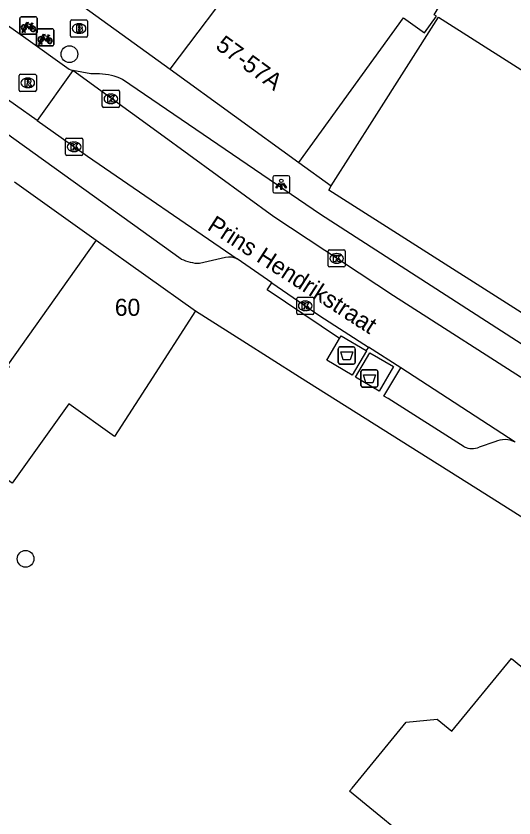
# Model space of a CAD drawing. Extents: x 160664 to 161506, y 382245 to 383288.
# Drawn here: x 161008.69 to 161037.82, y 383009.95 to 383056.85 of the extents above; entities that cross this region are included whole.
import ezdxf

# ---------------------------------------------------------------- set-up
doc = ezdxf.new("R2010")
doc.units = 0
for name, color, linetype in [('IMGEO_Afval_apart_plaats', 7, 'Continuous'), ('IMGEO_Boom', 7, 'Continuous'), ('IMGEO_Brandkraan', 7, 'Continuous'), ('IMGEO_Fietsenrek', 7, 'Continuous'), ('IMGEO_Kolk', 7, 'Continuous'), ('IMGEO_Lichtpunt', 7, 'Continuous'), ('IMGEO_Muur', 7, 'Continuous'), ('IMGEO_Openbare_ruimte_label', 7, 'Continuous'), ('IMGEO_Pand', 7, 'Continuous'), ('IMGEO_Pand_nummerreeks', 7, 'Continuous'), ('IMGEO_Rijbaan_lokaal_open', 7, 'Continuous'), ('IMGEO_Rioolput', 7, 'Continuous'), ('IMGEO_Voetpad_gesloten', 7, 'Continuous'), ('IMGEO_Voetpad_open', 7, 'Continuous')]:
    doc.layers.add(name, color=color, linetype=linetype)

msp = doc.modelspace()

# ---------------------------------------------------------------- linework, layer by layer
at = {"layer": 'IMGEO_Afval_apart_plaats'}
for p, q in [((161027.641, 383037.497), (161028.431, 383037.497)), ((161028.431, 383037.497), (161027.641, 383037.497)), ((161027.541, 383036.597), (161027.541, 383037.397)), ((161027.541, 383037.397), (161027.541, 383036.597)), ((161028.531, 383037.397), (161028.531, 383036.597)), ((161028.531, 383036.597), (161028.531, 383037.397)), ((161028.431, 383036.497), (161027.641, 383036.497)), ((161027.641, 383036.497), (161028.431, 383036.497)), ((161028.868, 383035.253), (161028.868, 383036.053)), ((161028.868, 383036.053), (161028.868, 383035.253)), ((161028.968, 383036.153), (161029.758, 383036.153)), ((161029.758, 383036.153), (161028.968, 383036.153)), ((161029.858, 383036.053), (161029.858, 383035.253)), ((161029.858, 383035.253), (161029.858, 383036.053)), ((161029.758, 383035.153), (161028.968, 383035.153)), ((161028.968, 383035.153), (161029.758, 383035.153))]:
    msp.add_line(p, q, dxfattribs=at)
for points in [[(161027.684, 383037.211), (161028.388, 383037.211), (161028.239, 383036.741), (161027.833, 383036.741), (161027.684, 383037.211)], [(161029.011, 383035.867), (161029.715, 383035.867), (161029.566, 383035.397), (161029.16, 383035.397), (161029.011, 383035.867)]]:
    msp.add_lwpolyline(points, dxfattribs=at)
for centre, start, end in [((161027.641, 383037.397), 90, 180), ((161027.641, 383037.397), 90, 180), ((161028.431, 383037.397), 0, 90), ((161028.431, 383037.397), 360, 90), ((161027.641, 383036.597), 180, 270), ((161027.641, 383036.597), 180, 270), ((161028.431, 383036.597), 270, 0), ((161028.431, 383036.597), 270, 0), ((161028.968, 383036.053), 90, 180), ((161028.968, 383036.053), 90, 180), ((161029.758, 383036.053), 0, 90), ((161029.758, 383036.053), 360, 90), ((161028.968, 383035.253), 180, 270), ((161028.968, 383035.253), 180, 270), ((161029.758, 383035.253), 270, 0), ((161029.758, 383035.253), 270, 0)]:
    msp.add_arc(centre, 0.1, start, end, dxfattribs=at)
at = {"layer": 'IMGEO_Boom'}
for centre in [(161011.813, 383054.621), (161009.25, 383025.106)]:
    msp.add_circle(centre, 0.489, dxfattribs=at)
at = {"layer": 'IMGEO_Brandkraan'}
for p, q in [((161011.877, 383055.695), (161011.877, 383056.547)), ((161011.952, 383056.621), (161012.804, 383056.621)), ((161012.365, 383056.401), (161012.39, 383056.401)), ((161012.878, 383056.547), (161012.878, 383055.695)), ((161012.388, 383055.841), (161012.363, 383055.841)), ((161012.804, 383055.621), (161011.952, 383055.621))]:
    msp.add_line(p, q, dxfattribs=at)
for points in [[(161011.877, 383055.695), (161011.877, 383056.547)], [(161011.952, 383056.621), (161012.804, 383056.621)], [(161012.225, 383056.321), (161012.225, 383055.921), (161012.438, 383055.921)], [(161012.456, 383056.321), (161012.225, 383056.321)], [(161012.404, 383056.24), (161012.35, 383056.24), (161012.35, 383056.164)], [(161012.878, 383056.547), (161012.878, 383055.695)], [(161012.35, 383056.164), (161012.403, 383056.164)], [(161012.412, 383056.088), (161012.35, 383056.088), (161012.35, 383056.007)], [(161012.35, 383056.007), (161012.412, 383056.007)], [(161012.804, 383055.621), (161011.952, 383055.621)]]:
    msp.add_lwpolyline(points, dxfattribs=at)
for centre, radius, start, end in [((161011.954, 383056.545), 0.0765, 91.552, 178.448), ((161011.954, 383056.545), 0.0765, 91.552, 178.448), ((161012.405, 383056.202), 0.0379, 267.8285, 90.9355), ((161012.46, 383056.176), 0.145, 59.4692, 91.5367), ((161012.485, 383056.223), 0.0922, 285.5137, 58.1501), ((161012.802, 383056.545), 0.0765, 1.552, 88.448), ((161012.802, 383056.545), 0.0765, 1.552, 88.448), ((161012.413, 383056.047), 0.0404, 269.8759, 90.5077), ((161012.444, 383056.172), 0.251, 268.6676, 293.5347), ((161012.49, 383056.031), 0.105, 301.3115, 78.989), ((161011.954, 383055.697), 0.0765, 181.552, 268.448), ((161011.954, 383055.697), 0.0765, 181.552, 268.448), ((161012.802, 383055.697), 0.0765, 271.552, 358.448), ((161012.802, 383055.697), 0.0765, 271.552, 358.448)]:
    msp.add_arc(centre, radius, start, end, dxfattribs=at)
for centre, major_axis, ratio, start_param, end_param in [((161012.364, 383056.121), (-0.387, 0.002), 0.722429, 4.712389, 7.853982), ((161012.389, 383056.121), (-0.39, 0.002), 0.717154, 1.570796, 4.712389)]:
    msp.add_ellipse(centre, major_axis=major_axis, ratio=ratio, start_param=start_param, end_param=end_param, dxfattribs=at)
at = {"layer": 'IMGEO_Fietsenrek'}
for p, q in [((161008.918, 383055.874), (161008.918, 383056.715)), ((161008.918, 383056.715), (161008.918, 383055.874)), ((161008.993, 383056.799), (161009.834, 383056.799)), ((161009.834, 383056.799), (161008.993, 383056.799)), ((161009.918, 383056.724), (161009.918, 383055.883)), ((161009.918, 383055.883), (161009.918, 383056.724)), ((161009.605, 383056.348), (161009.641, 383056.253)), ((161009.843, 383055.799), (161009.002, 383055.799)), ((161009.002, 383055.799), (161009.843, 383055.799)), ((161009.045, 383055.883), (161009.084, 383056.043)), ((161009.079, 383055.883), (161009.045, 383055.883)), ((161009.114, 383056.031), (161009.079, 383055.883)), ((161009.156, 383056.055), (161009.155, 383056.059)), ((161009.197, 383055.883), (161009.163, 383056.025)), ((161009.187, 383056.066), (161009.188, 383056.059)), ((161009.195, 383056.029), (161009.23, 383055.883)), ((161009.23, 383055.883), (161009.197, 383055.883)), ((161009.894, 383055.176), (161009.894, 383056.017)), ((161009.894, 383056.017), (161009.894, 383055.176)), ((161009.969, 383056.101), (161010.81, 383056.101)), ((161010.81, 383056.101), (161009.969, 383056.101)), ((161010.894, 383056.026), (161010.894, 383055.185)), ((161010.894, 383055.185), (161010.894, 383056.026)), ((161010.021, 383055.185), (161010.06, 383055.345)), ((161010.09, 383055.333), (161010.055, 383055.185)), ((161010.132, 383055.357), (161010.131, 383055.361)), ((161010.173, 383055.185), (161010.139, 383055.327)), ((161010.163, 383055.368), (161010.164, 383055.361)), ((161010.171, 383055.331), (161010.206, 383055.185)), ((161010.581, 383055.65), (161010.617, 383055.555)), ((161010.819, 383055.101), (161009.978, 383055.101)), ((161009.978, 383055.101), (161010.819, 383055.101)), ((161010.055, 383055.185), (161010.021, 383055.185)), ((161010.206, 383055.185), (161010.173, 383055.185))]:
    msp.add_line(p, q, dxfattribs=at)
for points in [[(161009.252, 383056.273), (161009.2, 383056.183), (161009.16, 383056.158), (161009.161, 383056.205), (161009.216, 383056.299)], [(161009.231, 383056.325), (161009.326, 383056.489), (161009.412, 383056.475), (161009.414, 383056.466), (161009.358, 383056.455), (161009.331, 383056.41), (161009.587, 383056.369)], [(161009.527, 383056.081), (161009.477, 383056.081), (161009.286, 383056.332), (161009.267, 383056.3)], [(161009.574, 383056.344), (161009.317, 383056.385), (161009.3, 383056.356), (161009.467, 383056.136), (161009.574, 383056.344)], [(161009.622, 383056.246), (161009.592, 383056.323), (161009.483, 383056.105), (161009.526, 383056.105)], [(161009.556, 383056.105), (161009.676, 383056.104), (161009.632, 383056.218)], [(161009.652, 383056.225), (161009.707, 383056.08), (161009.557, 383056.08)], [(161009.587, 383056.369), (161009.612, 383056.418), (161009.606, 383056.422), (161009.583, 383056.426), (161009.571, 383056.433), (161009.57, 383056.436), (161009.572, 383056.441), (161009.667, 383056.426), (161009.669, 383056.416), (161009.659, 383056.403), (161009.647, 383056.397), (161009.633, 383056.403), (161009.605, 383056.348)], [(161010.207, 383055.627), (161010.302, 383055.791), (161010.388, 383055.777), (161010.39, 383055.768), (161010.334, 383055.757), (161010.307, 383055.712), (161010.563, 383055.671)], [(161010.563, 383055.671), (161010.588, 383055.72), (161010.582, 383055.724), (161010.559, 383055.728), (161010.547, 383055.735), (161010.546, 383055.738), (161010.548, 383055.743), (161010.643, 383055.728), (161010.645, 383055.718), (161010.635, 383055.705), (161010.623, 383055.699), (161010.609, 383055.705), (161010.581, 383055.65)], [(161010.228, 383055.575), (161010.176, 383055.485), (161010.136, 383055.46), (161010.137, 383055.507), (161010.192, 383055.601)], [(161010.503, 383055.383), (161010.453, 383055.383), (161010.262, 383055.634), (161010.243, 383055.602)], [(161010.55, 383055.646), (161010.293, 383055.687), (161010.276, 383055.658), (161010.443, 383055.438), (161010.55, 383055.646)], [(161010.598, 383055.548), (161010.568, 383055.625), (161010.459, 383055.407), (161010.502, 383055.407)], [(161010.532, 383055.407), (161010.652, 383055.406), (161010.608, 383055.52)], [(161010.628, 383055.527), (161010.683, 383055.382), (161010.533, 383055.382)]]:
    msp.add_lwpolyline(points, dxfattribs=at)
for centre, radius, start, end in [((161008.996, 383056.721), 0.0779, 92.4484, 184.2845), ((161008.996, 383056.721), 0.0779, 92.4484, 184.2845), ((161009.84, 383056.721), 0.0779, 2.4484, 94.2845), ((161009.84, 383056.721), 0.0779, 2.4484, 94.2845), ((161009.158, 383056.184), 0.159, 62.6766, 242.1369), ((161009.158, 383056.184), 0.129, 63.3192, 238.903), ((161009.158, 383056.184), 0.129, 283.6043, 43.4302), ((161009.158, 383056.184), 0.159, 283.5766, 46.6042), ((161009.685, 383056.1), 0.159, 113.3408, 178.3217), ((161009.685, 383056.1), 0.159, 187.0065, 105.7708), ((161009.685, 383056.1), 0.129, 113.923, 177.9556), ((161009.685, 383056.1), 0.129, 188.6715, 104.5883), ((161008.996, 383055.877), 0.0779, 182.4484, 274.2845), ((161008.996, 383055.877), 0.0779, 182.4484, 274.2845), ((161009.138, 383056.055), 0.0499, 12.8025, 158.6934), ((161009.158, 383056.184), 0.159, 253.9967, 271.7867), ((161009.138, 383056.055), 0.0174, 12.8025, 163.4502), ((161009.158, 383056.184), 0.129, 253.415, 269.0204), ((161009.84, 383055.877), 0.0779, 272.4484, 4.2845), ((161009.84, 383055.877), 0.0779, 272.4484, 4.2845), ((161009.972, 383056.023), 0.0779, 92.4484, 184.2845), ((161009.972, 383056.023), 0.0779, 92.4484, 184.2845), ((161010.816, 383056.023), 0.0779, 2.4484, 94.2845), ((161010.816, 383056.023), 0.0779, 2.4484, 94.2845), ((161010.134, 383055.486), 0.159, 62.6766, 242.1369), ((161010.134, 383055.486), 0.129, 63.3192, 238.903), ((161010.114, 383055.357), 0.0499, 12.8025, 158.6934), ((161010.134, 383055.486), 0.159, 253.9967, 271.7867), ((161010.114, 383055.357), 0.0174, 12.8025, 163.4502), ((161010.134, 383055.486), 0.129, 253.415, 269.0204), ((161010.134, 383055.486), 0.129, 283.6043, 43.4302), ((161010.134, 383055.486), 0.159, 283.5766, 46.6042), ((161010.661, 383055.402), 0.159, 113.3408, 178.3217), ((161010.661, 383055.402), 0.159, 187.0065, 105.7708), ((161010.661, 383055.402), 0.129, 113.923, 177.9556), ((161010.661, 383055.402), 0.129, 188.6715, 104.5883), ((161009.972, 383055.179), 0.0779, 182.4484, 274.2845), ((161009.972, 383055.179), 0.0779, 182.4484, 274.2845), ((161010.816, 383055.179), 0.0779, 272.4484, 4.2845), ((161010.816, 383055.179), 0.0779, 272.4484, 4.2845)]:
    msp.add_arc(centre, radius, start, end, dxfattribs=at)
at = {"layer": 'IMGEO_Kolk'}
for p, q in [((161013.813, 383052.509), (161014.665, 383052.509)), ((161013.738, 383051.583), (161013.738, 383052.435)), ((161014.226, 383052.289), (161014.251, 383052.289)), ((161014.739, 383052.435), (161014.739, 383051.583)), ((161014.665, 383051.509), (161013.813, 383051.509)), ((161014.249, 383051.729), (161014.224, 383051.729)), ((161011.59, 383048.777), (161011.59, 383049.629)), ((161011.665, 383049.703), (161012.517, 383049.703)), ((161012.591, 383049.629), (161012.591, 383048.777)), ((161012.078, 383049.483), (161012.103, 383049.483)), ((161012.517, 383048.703), (161011.665, 383048.703)), ((161012.101, 383048.923), (161012.076, 383048.923)), ((161026.947, 383042.249), (161026.947, 383043.101)), ((161027.022, 383043.175), (161027.874, 383043.175)), ((161027.948, 383043.101), (161027.948, 383042.249)), ((161027.435, 383042.955), (161027.46, 383042.955)), ((161027.874, 383042.175), (161027.022, 383042.175)), ((161027.458, 383042.395), (161027.433, 383042.395)), ((161025.109, 383039.476), (161025.109, 383040.328)), ((161025.184, 383040.402), (161026.036, 383040.402)), ((161026.11, 383040.328), (161026.11, 383039.476)), ((161025.597, 383040.182), (161025.622, 383040.182)), ((161026.036, 383039.402), (161025.184, 383039.402)), ((161025.62, 383039.622), (161025.595, 383039.622))]:
    msp.add_line(p, q, dxfattribs=at)
for points in [[(161013.813, 383052.509), (161014.665, 383052.509)], [(161013.738, 383051.583), (161013.738, 383052.435)], [(161014.059, 383052.209), (161014.182, 383052.209), (161014.182, 383052.058), (161014.312, 383052.209), (161014.476, 383052.209), (161014.33, 383052.058), (161014.483, 383051.809), (161014.331, 383051.809), (161014.246, 383051.973), (161014.182, 383051.906), (161014.182, 383051.809), (161014.059, 383051.809), (161014.059, 383052.209)], [(161014.739, 383052.435), (161014.739, 383051.583)], [(161014.665, 383051.509), (161013.813, 383051.509)], [(161011.59, 383048.777), (161011.59, 383049.629)], [(161011.665, 383049.703), (161012.517, 383049.703)], [(161012.591, 383049.629), (161012.591, 383048.777)], [(161011.911, 383049.403), (161012.034, 383049.403), (161012.034, 383049.252), (161012.164, 383049.403), (161012.328, 383049.403), (161012.182, 383049.252), (161012.335, 383049.003), (161012.183, 383049.003), (161012.098, 383049.167), (161012.034, 383049.1), (161012.034, 383049.003), (161011.911, 383049.003), (161011.911, 383049.403)], [(161012.517, 383048.703), (161011.665, 383048.703)], [(161026.947, 383042.249), (161026.947, 383043.101)], [(161027.022, 383043.175), (161027.874, 383043.175)], [(161027.948, 383043.101), (161027.948, 383042.249)], [(161027.268, 383042.875), (161027.391, 383042.875), (161027.391, 383042.724), (161027.521, 383042.875), (161027.685, 383042.875), (161027.539, 383042.724), (161027.692, 383042.475), (161027.54, 383042.475), (161027.455, 383042.639), (161027.391, 383042.572), (161027.391, 383042.475), (161027.268, 383042.475), (161027.268, 383042.875)], [(161027.874, 383042.175), (161027.022, 383042.175)], [(161025.109, 383039.476), (161025.109, 383040.328)], [(161025.184, 383040.402), (161026.036, 383040.402)], [(161026.11, 383040.328), (161026.11, 383039.476)], [(161025.43, 383040.102), (161025.553, 383040.102), (161025.553, 383039.951), (161025.683, 383040.102), (161025.847, 383040.102), (161025.701, 383039.951), (161025.854, 383039.702), (161025.702, 383039.702), (161025.617, 383039.866), (161025.553, 383039.799), (161025.553, 383039.702), (161025.43, 383039.702), (161025.43, 383040.102)], [(161026.036, 383039.402), (161025.184, 383039.402)]]:
    msp.add_lwpolyline(points, dxfattribs=at)
for centre, start, end in [((161013.815, 383052.433), 91.552, 178.448), ((161013.815, 383052.433), 91.552, 178.448), ((161014.663, 383052.433), 1.552, 88.448), ((161014.663, 383052.433), 1.552, 88.448), ((161013.815, 383051.585), 181.552, 268.448), ((161013.815, 383051.585), 181.552, 268.448), ((161014.663, 383051.585), 271.552, 358.448), ((161014.663, 383051.585), 271.552, 358.448), ((161011.667, 383049.627), 91.552, 178.448), ((161011.667, 383049.627), 91.552, 178.448), ((161012.515, 383049.627), 1.552, 88.448), ((161012.515, 383049.627), 1.552, 88.448), ((161011.667, 383048.779), 181.552, 268.448), ((161011.667, 383048.779), 181.552, 268.448), ((161012.515, 383048.779), 271.552, 358.448), ((161012.515, 383048.779), 271.552, 358.448), ((161027.024, 383043.099), 91.552, 178.448), ((161027.024, 383043.099), 91.552, 178.448), ((161027.872, 383043.099), 1.552, 88.448), ((161027.872, 383043.099), 1.552, 88.448), ((161027.024, 383042.251), 181.552, 268.448), ((161027.024, 383042.251), 181.552, 268.448), ((161027.872, 383042.251), 271.552, 358.448), ((161027.872, 383042.251), 271.552, 358.448), ((161025.186, 383040.326), 91.552, 178.448), ((161025.186, 383040.326), 91.552, 178.448), ((161026.034, 383040.326), 1.552, 88.448), ((161026.034, 383040.326), 1.552, 88.448), ((161025.186, 383039.478), 181.552, 268.448), ((161025.186, 383039.478), 181.552, 268.448), ((161026.034, 383039.478), 271.552, 358.448), ((161026.034, 383039.478), 271.552, 358.448)]:
    msp.add_arc(centre, 0.0765, start, end, dxfattribs=at)
for centre, major_axis, ratio, start_param, end_param in [((161014.225, 383052.009), (-0.387, 0.002), 0.722429, 4.712389, 7.853982), ((161014.25, 383052.009), (-0.39, 0.002), 0.717154, 1.570796, 4.712389), ((161012.077, 383049.203), (-0.387, 0.002), 0.722429, 4.712389, 7.853982), ((161012.102, 383049.203), (-0.39, 0.002), 0.717154, 1.570796, 4.712389), ((161027.434, 383042.675), (-0.387, 0.002), 0.722429, 4.712389, 7.853982), ((161027.459, 383042.675), (-0.39, 0.002), 0.717154, 1.570796, 4.712389), ((161025.596, 383039.902), (-0.387, 0.002), 0.722429, 4.712389, 7.853982), ((161025.621, 383039.902), (-0.39, 0.002), 0.717154, 1.570796, 4.712389)]:
    msp.add_ellipse(centre, major_axis=major_axis, ratio=ratio, start_param=start_param, end_param=end_param, dxfattribs=at)
at = {"layer": 'IMGEO_Lichtpunt'}
for p, q in [((161023.71, 383047.414), (161023.71, 383046.607)), ((161023.71, 383047.414), (161023.71, 383046.607)), ((161024.612, 383047.509), (161023.804, 383047.509)), ((161024.612, 383047.509), (161023.804, 383047.509)), ((161024.706, 383046.607), (161024.706, 383047.414)), ((161024.706, 383046.607), (161024.706, 383047.414)), ((161023.804, 383046.513), (161024.612, 383046.513)), ((161023.804, 383046.513), (161024.612, 383046.513))]:
    msp.add_line(p, q, dxfattribs=at)
for points in [[(161024.084, 383047.078), (161024.123, 383047.05), (161023.935, 383046.788), (161023.897, 383046.815), (161024.084, 383047.078)], [(161024.186, 383047.03), (161024.233, 383047.03), (161024.233, 383046.708), (161024.186, 383046.708), (161024.186, 383047.03)], [(161024.296, 383047.05), (161024.334, 383047.077), (161024.521, 383046.815), (161024.482, 383046.787), (161024.296, 383047.05)]]:
    msp.add_lwpolyline(points, dxfattribs=at)
msp.add_circle((161024.209, 383047.212), 0.0994, dxfattribs=at)
for centre, start, end in [((161023.804, 383047.414), 90, 180), ((161023.804, 383047.414), 90, 180), ((161024.612, 383047.414), 0, 90), ((161024.612, 383047.414), 0, 90), ((161023.804, 383046.607), 180, 270), ((161023.804, 383046.607), 180, 270), ((161024.612, 383046.607), 270, 0), ((161024.612, 383046.607), 270, 360)]:
    msp.add_arc(centre, 0.0946, start, end, dxfattribs=at)
at = {"layer": 'IMGEO_Muur'}
for points in [[(161019.187, 383039.602), (161021.951, 383037.858)], [(161025.283, 383035.755), (161036.108, 383028.925)]]:
    msp.add_lwpolyline(points, dxfattribs=at)
at = {"layer": 'IMGEO_Pand'}
for points in [[(161025.238, 383048.281), (161031.36, 383056.746), (161032.578, 383055.865), (161033.282, 383056.839), (161033.159, 383056.928), (161037.886, 383064.946), (161033.964, 383067.181), (161029.085, 383058.618), (161027.911, 383059.467), (161029.876, 383062.184)], [(161017.714, 383053.743), (161026.317, 383065.155)], [(161011.26, 383058.428), (161017.714, 383053.743)], [(161027.134, 383046.913), (161029.664, 383050.891), (161033.411, 383056.782), (161048.444, 383047.224)], [(161017.714, 383053.743), (161025.238, 383048.281)], [(161008.601, 383047.148), (161013.371, 383043.748)], [(161049.305, 383032.471), (161048.411, 383033.039), (161026.98, 383046.672), (161027.134, 383046.913)], [(161013.371, 383043.748), (161008.196, 383036.426), (161008.293, 383036.357), (161005.048, 383031.915)], [(161013.371, 383043.748), (161019.187, 383039.602)], [(161019.187, 383039.602), (161016.476, 383035.398), (161014.456, 383032.264), (161011.776, 383034.175), (161008.461, 383029.525), (161005.851, 383031.386), (161005.162, 383030.419), (161004.845, 383030.645), (161004.379, 383030.977), (161005.048, 383031.915)], [(161035.066, 383007.264), (161033.307, 383008.711), (161032.628, 383007.886), (161028.208, 383011.521), (161028.345, 383011.687), (161031.521, 383015.548), (161033.334, 383015.724), (161034.176, 383015.032), (161037.672, 383019.283), (161043.618, 383014.393)]]:
    msp.add_lwpolyline(points, dxfattribs=at)
at = {"layer": 'IMGEO_Rijbaan_lokaal_open'}
for points in [[(161008.196, 383056.32), (161009.257, 383055.551), (161011.79, 383053.75), (161011.903, 383053.709), (161012.017, 383053.67)], [(161009.922, 383050.733), (161006.105, 383053.424)], [(161012.017, 383053.67), (161009.922, 383050.733)], [(161060.074, 383021.752), (161056.443, 383024.051), (161047.653, 383029.663), (161039.174, 383035.116), (161030.766, 383040.479), (161023.767, 383045.113), (161017.137, 383049.948), (161012.017, 383053.67)], [(161009.922, 383050.733), (161012.871, 383048.655), (161021.62, 383042.643)], [(161023.653, 383041.246), (161021.62, 383042.643)], [(161023.653, 383041.246), (161026.46, 383039.316), (161029.303, 383037.478)], [(161031.195, 383036.275), (161029.303, 383037.478)], [(161037.89, 383031.927), (161031.195, 383036.275)]]:
    msp.add_lwpolyline(points, dxfattribs=at)
at = {"layer": 'IMGEO_Rioolput'}
for p, q in [((161008.952, 383053.443), (161009.804, 383053.443)), ((161008.877, 383052.517), (161008.877, 383053.369)), ((161009.365, 383053.223), (161009.39, 383053.223)), ((161009.878, 383053.369), (161009.878, 383052.517)), ((161009.804, 383052.443), (161008.952, 383052.443)), ((161009.388, 383052.663), (161009.363, 383052.663))]:
    msp.add_line(p, q, dxfattribs=at)
for points in [[(161008.952, 383053.443), (161009.804, 383053.443)], [(161008.877, 383052.517), (161008.877, 383053.369)], [(161009.466, 383053.141), (161009.214, 383053.143), (161009.214, 383052.743)], [(161009.392, 383053.062), (161009.338, 383053.062), (161009.338, 383052.981)], [(161009.338, 383052.981), (161009.39, 383052.981)], [(161009.878, 383053.369), (161009.878, 383052.517)], [(161009.804, 383052.443), (161008.952, 383052.443)], [(161009.214, 383052.743), (161009.338, 383052.743), (161009.338, 383052.905), (161009.349, 383052.905)], [(161009.396, 383052.876), (161009.467, 383052.743), (161009.607, 383052.743), (161009.542, 383052.869)]]:
    msp.add_lwpolyline(points, dxfattribs=at)
for centre, radius, start, end in [((161008.954, 383053.367), 0.0765, 91.552, 178.448), ((161008.954, 383053.367), 0.0765, 91.552, 178.448), ((161009.802, 383053.367), 0.0765, 1.552, 88.448), ((161009.802, 383053.367), 0.0765, 1.552, 88.448), ((161009.374, 383053.17), 0.19, 274.7715, 282.9687), ((161009.398, 383052.966), 0.0964, 77.0061, 93.1865), ((161009.412, 383053.023), 0.0378, 276.6634, 79.6772), ((161009.465, 383053.031), 0.109, 350.3612, 89.416), ((161009.463, 383053.031), 0.112, 277.5842, 350.9817), ((161009.447, 383052.816), 0.108, 29.5134, 73.7905), ((161008.954, 383052.519), 0.0765, 181.552, 268.448), ((161008.954, 383052.519), 0.0765, 181.552, 268.448), ((161009.348, 383052.852), 0.0533, 26.0293, 88.6989), ((161009.802, 383052.519), 0.0765, 271.552, 358.448), ((161009.802, 383052.519), 0.0765, 271.552, 358.448)]:
    msp.add_arc(centre, radius, start, end, dxfattribs=at)
for centre, major_axis, ratio, start_param, end_param in [((161009.364, 383052.943), (-0.387, 0.002), 0.722429, 4.712389, 7.853982), ((161009.389, 383052.943), (-0.39, 0.002), 0.717154, 1.570796, 4.712389)]:
    msp.add_ellipse(centre, major_axis=major_axis, ratio=ratio, start_param=start_param, end_param=end_param, dxfattribs=at)
at = {"layer": 'IMGEO_Voetpad_gesloten'}
for points in [[(161029.178, 383037.29), (161029.202, 383037.276), (161028.358, 383035.842), (161026.87, 383036.718), (161027.623, 383037.998)], [(161027.623, 383037.998), (161027.714, 383038.152), (161029.178, 383037.29)], [(161030.772, 383036.352), (161029.928, 383034.918), (161028.55, 383035.729), (161029.394, 383037.163), (161030.772, 383036.352)]]:
    msp.add_lwpolyline(points, dxfattribs=at)
at = {"layer": 'IMGEO_Voetpad_open'}
for points in [[(161018.351, 383042.641), (161000, 383055.808), (160999.215, 383056.323)], [(161013.579, 383053.465), (161013.058, 383053.465), (161012.017, 383053.67)], [(161059.441, 383023.143), (161059.314, 383023.651), (161058.871, 383024.388), (161026.498, 383045.25), (161014.924, 383053.146)], [(161025.238, 383048.281), (161027.134, 383046.913)], [(161020.943, 383042.728), (161019.421, 383042.388)], [(161027.623, 383037.998), (161023.373, 383040.832), (161023.653, 383041.246)], [(161019.187, 383039.602), (161021.951, 383037.858), (161025.283, 383035.755), (161036.108, 383028.925), (161039.5, 383026.785), (161043.678, 383024.149), (161048.921, 383020.84)], [(161029.303, 383037.478), (161029.178, 383037.29)], [(161034.909, 383031.662), (161030.461, 383034.476), (161030.201, 383034.629), (161030.258, 383034.723), (161031.195, 383036.275)], [(161036.709, 383031.945), (161035.784, 383031.642)]]:
    msp.add_lwpolyline(points, dxfattribs=at)
for centre, radius, start, end in [((161013.464, 383049.983), 3.483, 65.2133, 88.1015), ((161019.45, 383044.899), 2.511, 244.0497, 269.3439), ((161021.153, 383041.663), 1.086, 64.5335, 101.1539), ((161037.282, 383030.815), 1.267, 61.3505, 116.9031), ((161035.367, 383032.539), 0.989, 242.4423, 294.9389)]:
    msp.add_arc(centre, radius, start, end, dxfattribs=at)

# ---------------------------------------------------------------- texts
at = {"layer": 'IMGEO_Openbare_ruimte_label'}
msp.add_text('Prins Hendrikstraat', height=1, rotation=327.1202, dxfattribs=at).set_placement((161019.82, 383044.396))
at = {"layer": 'IMGEO_Pand_nummerreeks'}
msp.add_text('57-57A', height=1, rotation=324.024, dxfattribs=at).set_placement((161020.303, 383054.978))
msp.add_text('60', height=1, dxfattribs=at).set_placement((161014.47, 383039.317))

doc.saveas('drawing.dxf')
